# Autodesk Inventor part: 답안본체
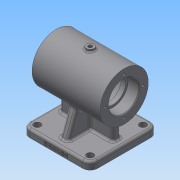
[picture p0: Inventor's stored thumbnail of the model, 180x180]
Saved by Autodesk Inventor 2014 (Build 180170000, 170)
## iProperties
Created: 2019-06
Part Number: 답안본체
Material: 일반
Document SubType Name: Modeling
Designer: NET
Density: 1 g/cm^3
Appearance: 기본값
Author: NET
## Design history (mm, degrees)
sketch "스케치1"
  geometry: L1 (45, 0)-(-45, 0); L2 (45, 0)-(45, 32); L3 (45, 32)-(-45, 32); L4 (-45, 32)-(-45, 0); L5 (45, 20)-(30.3, 20); L6 (30, 19.7)-(30, 17); L7 (30, 17)-(24, 17); L8 (24, 17)-(24, 22); L9 (21, 25)-(-21, 25); L10 (-24, 22)-(-24, 17); L11 (-24, 17)-(-30, 17); L12 (-30, 17)-(-30, 19.7); L13 (-30.3, 20)-(-45, 20); A1 r 0.3 centre (30.3, 19.7) between (30.3, 20) and (30, 19.7); A2 r 0.3 centre (-30.3, 19.7) between (-30, 19.7) and (-30.3, 20); A3 r 3 centre (21, 22) between (24, 22) and (21, 25); A4 r 3 centre (-21, 22) between (-21, 25) and (-24, 22); 5 further points
  constraints: 26 end point, 8 point on circle, 8 point on line, 8 tangent, 7 parallel, 5 perpendicular, 4 centre point, 2 equal radius, 1 coincident, 1 horizontal, 1 midpoint
  dimensions: "d0" = 90 distance of L1.start L1.end; "d1" = 64 diameter of L3 L1; "d2" = 48 distance of point (24, 25) point (-24, 25); "d3" = 50 diameter of L9 L1; "d4" = 15 distance of L5.start point (30, 20); "d5" = 40 diameter of L5 L1; "d6" = 34 diameter of L7 L1; "d7" = 6 distance of L6.end L7.end; "d8" = 6 distance of L10.end L11.end; "d9" = 34 diameter of L11 L1; "d10" = 40 diameter of L13 L1; "d11" = 0.3 radius of A1; "d12" = 3 radius of A3
revolve "회전1" sketch "스케치1" stored, may be unused: angle "d13" = 90 deg
chamfer "모따기1" distance "d14" = 1; stored, may be unused: second distance "d15" = 2, angle "d16" = 45 deg
node "작업 평면1"
sketch "스케치2"
  geometry: C1 r 5 at (0, 0); 1 further point
  constraints: 1 centre point, 1 coincident
  dimensions: "d18" = 10 diameter of C1
extrude "돌출1" join sketch "스케치2" stored distance "d19" = 10; taper "d20" = 0 deg
sketch "스케치3"
  geometry: C1 r 5 at (0, 0) reference; 1 further point
  constraints: 1 coincident
hole "구멍1" sketch "스케치3" at (0, 0) diameter "d21" = 4.917; stored, may be unused: countersink angle "d25" = 90 deg, drill point angle "d27" = 118 deg; dims "d22" = 6, "d23" = 4, "d24" = 2, "d26" = 20
fillet "모깎기1" dims "d28" = 2
node "작업 평면2"
sketch "스케치4"
  geometry: L1 (-45, -45)-(45, -45); L2 (45, -45)-(45, 45); L3 (45, 45)-(-45, 45); L4 (-45, 45)-(-45, -45); L5 (-45, -45)-(45, 45); L6 (45, -45)-(-45, 45); 1 further point
  constraints: 12 end point, 2 midpoint, 2 parallel, 1 horizontal, 1 perpendicular
  dimensions: "d30" = 90 distance of L2.end L3.end; "d31" = 90 distance of L1.end L2.end
extrude "돌출2" join sketch "스케치4" distance "d32" = 10; taper "d33" = 0 deg
fillet "모깎기2" dims "d34" = 10
fillet "모깎기3" dims "d35" = 3
sketch "스케치5"
  geometry: L1 (-35, -5)-(35, -5); L2 (35, -5)-(35, 5); L3 (35, 5)-(-35, 5); L4 (-35, 5)-(-35, -5); L5 (-35, -5)-(35, 5); L6 (35, -5)-(-35, 5); 1 further point
  constraints: 12 end point, 2 midpoint, 2 parallel, 1 horizontal, 1 perpendicular
  dimensions: "d36" = 10 distance between parallel lines of L3 L1; "d37" = 70 distance of L1.start L1.end
extrude "돌출3" join sketch "스케치5" stored distance "d38" = 10; taper "d39" = 0 deg
sketch "스케치6"
  geometry: L1 (45, -58)-(45, -65) reference; L2 (45, -65)-(-45, -65) reference; L3 (-45, -65)-(-45, -58) reference; L4 (-42, -55)-(-5, -55) reference; L5 (-5, -55)-(-5, -31.607) reference; L6 (-5, 33.272)-(-5, 35) reference; L7 (-5, 35)-(-2.458, 35) reference; L8 (-2.458, 35)-(-2.458, 24.879) reference; L9 (2.458, 24.879)-(2.458, 35) reference; L10 (2.458, 35)-(5, 35) reference; L11 (5, 35)-(5, 33.272) reference; L12 (5, -31.607)-(5, -55) reference; L13 (5, -55)-(42, -55) reference; L14 (-35, -55)-(-23.058, -22.189); A1 r 3 centre (42, -58) between (45, -58) and (42, -55) reference; A2 r 3 centre (-42, -58) between (-42, -55) and (-45, -58) reference; A3 r 32 centre (0, 0) between (-6.588, 31.314) and (-5, -31.607) reference; A4 r 25 centre (0, 0) between (-2.458, 24.879) and (2.458, 24.879) reference; A5 r 32 centre (0, 0) between (5, -31.607) and (6.588, 31.314) reference; 1 further point
  constraints: 2 end point, 1 point on circle, 1 point on line, 2 other
  dimensions: "d41" = 110 deg angle of L4 L14; "d42" = 10 distance from line of L14.start L3
feature "리브1" sketch "스케치6" dims "d43" = 1, "d44" = 10, "d45" = 0, "d46" = 0, "d47" = 1, "d48" = 1
fillet "모깎기4" dims "d49" = 3
fillet "모깎기5" dims "d50" = 3
fillet "모깎기6" dims "d51" = 3
fillet "모깎기7" dims "d52" = 3
fillet "모깎기8" dims "d53" = 3
fillet "모깎기9" dims "d54" = 3
fillet "모깎기10" dims "d55" = 3
fillet "모깎기11" dims "d56" = 3
fillet "모깎기12" dims "d57" = 3
sketch "스케치7"
  geometry: C1 r 4.5 at (-35, 35); C2 r 4.5 at (-35, -35); A1 r 7 centre (-35, 35) between (-35, 42) and (-42, 35) reference; A2 r 7 centre (-35, -35) between (-42, -35) and (-35, -42) reference; 1 further point
  constraints: 2 centre point, 2 coincident
  dimensions: "d58" = 9 diameter of C1; "d59" = 9 diameter of C2
extrude "돌출4" cut sketch "스케치7" distance "d60" = 35; taper "d61" = 0 deg
sketch "스케치8"
  geometry: C1 r 32 at (0, 0) reference; 1 further point
  constraints: 1 horizontal alignment
  dimensions: "d63" = 25 distance of C1.centre point (-25, 0)
hole "구멍2" sketch "스케치8" at (-25, 0) diameter "d64" = 3.242; stored, may be unused: countersink angle "d68" = 90 deg, drill point angle "d70" = 118 deg; dims "d65" = 7, "d66" = 4, "d67" = 2, "d69" = 9
sketch "스케치9"
  geometry: L1 (0, 0)-(70, 0) reference; L2 (-10, 7)-(-10, 0) reference; 2 further points
  constraints: 1 other
  dimensions: "d74" = 4 distance from line of point (35, 4) L1; "d75" = 45 distance from line of point (35, 4) L2
feature "엠보싱1" sketch "스케치9" dims "d0" = 90, "d1" = 64, "d2" = 48, "d3" = 50, "d4" = 15, "d5" = 40, "d6" = 34, "d7" = 6, "d8" = 6, "d9" = 34, "d10" = 40, "d11" = 0.3, "d12" = 3, "d76" = 0.5, "d77" = 0
sketch "스케치10" dims "d80" = 20
  geometry: L1 (35, -45)-(-35, -45) reference; L2 (45, 35)-(45, -35) reference; L3 (-22, -40)-(22, -40); L4 (40, -22)-(40, 22); L5 (-40, 22)-(-40, -22); L6 (-40, -40)-(40, 40); L7 (40, -40)-(-40, 40); L8 (-25, -37)-(-25, -35); L9 (-37, -25)-(-35, -25); L10 (-37, 25)-(-35, 25); L11 (-25, 35)-(-25, 37); L12 (22, 40)-(-22, 40); L13 (-26.34, 40)-(-40, 40); L14 (25, 37)-(25, 35); L15 (35, 25)-(37, 25); L16 (25, -37)-(25, -35); L17 (35, -25)-(37, -25); C1 r 10 at (35, 35); C2 r 10 at (-35, -35); C3 r 10 at (35, -35); A1 r 10 centre (35, -35) between (35, -45) and (45, -35) reference; A2 r 10 centre (35, 35) between (45, 35) and (35, 45) reference; A3 r 10 centre (-35, 35) between (-35, 45) and (-45, 35) reference; A4 r 10 centre (-35, -35) between (-45, -35) and (-35, -45) reference; A5 r 10 centre (-35, 35) between (-35, 25) and (-25, 35); A6 r 10 centre (35, 35) between (25, 35) and (35, 25); A7 r 10 centre (35, -35) between (35, -25) and (25, -35); A8 r 10 centre (-35, -35) between (-25, -35) and (-35, -25); A9 r 3 centre (-37, -22) between (-40, -22) and (-37, -25); A10 r 3 centre (-22, -37) between (-25, -37) and (-22, -40); A11 r 3 centre (37, 22) between (40, 22) and (37, 25); A12 r 3 centre (22, 37) between (25, 37) and (22, 40); A13 r 3 centre (-37, 22) between (-37, 25) and (-40, 22); A14 r 3 centre (-22, 37) between (-22, 40) and (-25, 37); A15 r 3 centre (37, -22) between (37, -25) and (40, -22); A16 r 3 centre (22, -37) between (22, -40) and (25, -37); 3 further points
  constraints: 30 end point, 30 tangent, 24 point on circle, 15 centre point, 8 perpendicular, 5 parallel, 5 point on line, 4 coincident, 3 equal radius, 2 horizontal, 2 midpoint, 1 vertical, 3 other
  dimensions: "d78" = 80 distance of L6.end L7.end; "d79" = 80 distance of L7.start L6.end; "d81" = 20 diameter of C1; "d82" = 20 diameter of C2; "d83" = 20 diameter of C3; "d85" = 10 radius of A5; "d86" = 3 radius of A9; "d87" = 3 radius of A10; "d88" = 3 radius of A11; "d89" = 3 radius of A12; "d90" = 3 radius of A13; "d91" = 3 radius of A14; "d92" = 3 radius of A15; "d93" = 3 radius of A16; "d94" = 5 distance between parallel lines of L2 L4; "d95" = 85 distance between parallel lines of L2 L5; "d96" = 85 distance between parallel lines of L1 L12; "d97" = 85 distance from line of L6.start L2
extrude "돌출5" cut sketch "스케치10" distance "d98" = 5; taper "d99" = 0 deg
node "솔리드1"
mirror "대칭1"
mirror "대칭2"
pattern_circular "원형 패턴1" dims angle "d72" = 360 deg
mirror "대칭3"
node "절단 모서리 투영1"
other parameters: "d17" = 35, "d29" = -65
